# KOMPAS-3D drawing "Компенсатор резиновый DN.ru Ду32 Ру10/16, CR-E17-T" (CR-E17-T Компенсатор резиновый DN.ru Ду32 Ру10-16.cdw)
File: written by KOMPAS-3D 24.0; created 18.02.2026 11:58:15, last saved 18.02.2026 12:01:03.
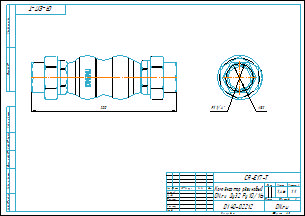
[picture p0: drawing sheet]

Document properties: Типовые: Типовые; Автор: DN.RU; Форматы листов документа: A3; Полное имя файла: CR-E17-T Компенсатор резиновый DN.ru Ду32 Ру10-16.m3d; Масса: 1.46; Наименование: Компенсатор резиновый DN.ru Ду32 Ру10/16; Количество листов документа: 1; Комментарий: D140-02212; Примечание: D140-02212

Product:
- Body: Твердое тело1  | qty 1
    Масса: 1.835825
- Part/product: Компенсатор резиновый DN.ru Ду32 Ру10/16  | designation CR-E17-T
    Масса: 1.46
    Раздел спецификации: Прочие изделия
    Форматы листов документа: A3
    Комментарий: D140-02212
    Примечание: D140-02212
    additional columns: Типовые

Views: Вид 1, Справа, Проекционный вид 2
Referenced files in D:\Работа\Компенсаторы\CR-Е17-T Компенсатор резиновый DN.ru Ду15-80\DN32\: CR-E17-T Компенсатор резиновый DN.ru Ду32 Ру10-16.m3d, CR-E17-T Компенсатор резиновый DN.ru Ду32 Ру10-16.cdw
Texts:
  Линейный размер
  CR-E17-T
  Диаметральный размер
  Компенсатор резиновый
  DN.ru Ду32 Ру10/16
  Твердое тело1
  Компенсатор резиновый DN.ru Ду32 Ру10/16
  CR-E17-T Компенсатор резиновый DN.ru Ду32 Ру10/16
Dimensions and other numbers on the sheet: 0; 3; 2; 4; 200; 32; 1:1; 1; 1,46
